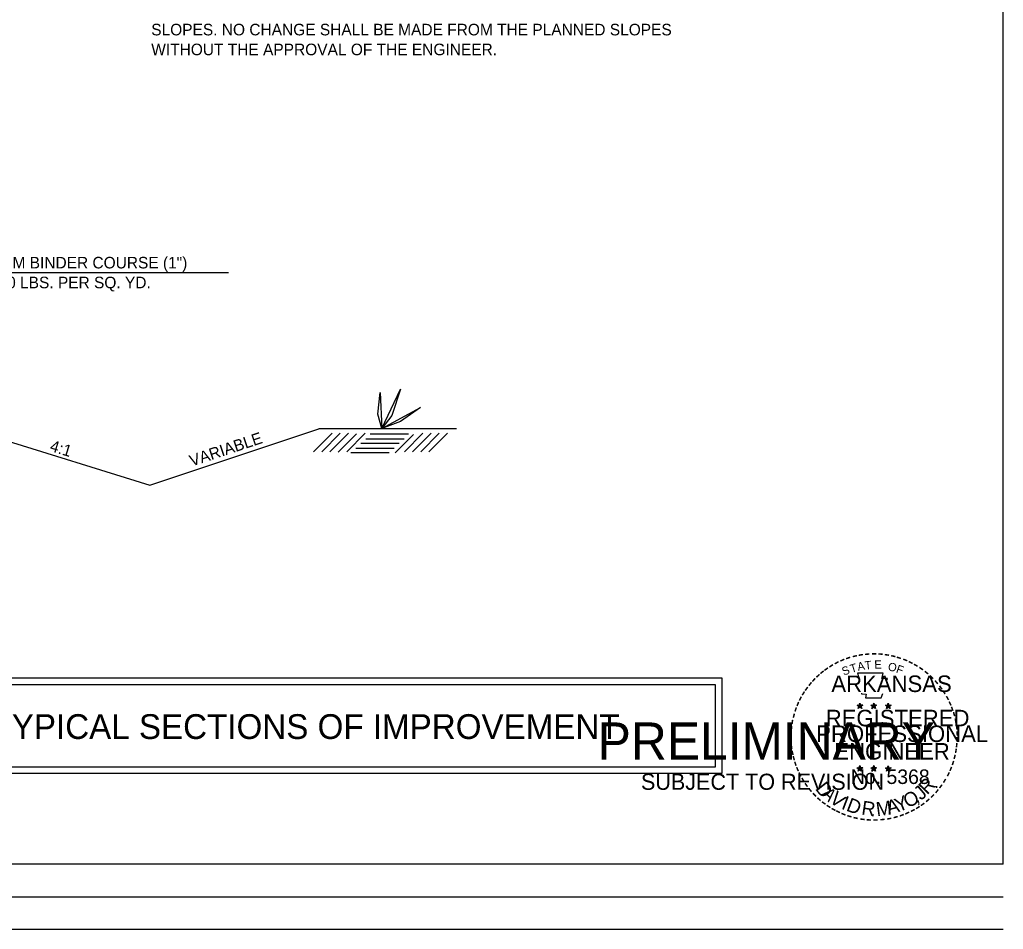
# Model space of a CAD drawing. Extents: x 1944905 to 1956777, y 763871 to 764977.
# Drawn here: x 1945928 to 1946523, y 763871 to 764421 of the extents above; entities that cross this region are included whole.
import ezdxf

# ---------------------------------------------------------------- set-up
doc = ezdxf.new("R2010")
doc.units = 0
doc.layers.add('Default', color=7, linetype='Continuous')
doc.layers.add('R_Border PE', color=7, linetype='Continuous')

msp = doc.modelspace()

# ---------------------------------------------------------------- linework, layer by layer
at = {"layer": 'Default'}
for p, q in [((1946523.23, 763910.07), (1946523.23, 764937.29)), ((1945703.81, 764268.09), (1946054.49, 764268.09)), ((1946144.78, 764182.39), (1946146.22, 764195.62)), ((1946146.22, 764195.62), (1946147.19, 764173.75)), ((1946147.19, 764173.75), (1946158.48, 764197.54)), ((1946158.48, 764197.54), (1946153.19, 764181.67)), ((1946147.19, 764173.75), (1946170.49, 764186.48)), ((1946170.49, 764186.48), (1946158.48, 764178.07)), ((1945878.1, 764179.33), (1946006.89, 764139.54)), ((1946147.19, 764173.75), (1946144.78, 764182.39)), ((1946153.19, 764181.67), (1946147.19, 764173.75)), ((1946158.48, 764178.07), (1946147.19, 764173.75)), ((1946006.89, 764139.54), (1946108.97, 764173.57)), ((1946117.08, 764170.92), (1946105.89, 764159.72)), ((1946192.37, 764173.57), (1946108.97, 764173.57)), ((1946122.02, 764170.92), (1946110.82, 764159.72)), ((1946126.95, 764170.92), (1946115.76, 764159.72)), ((1946137.18, 764170.92), (1946125.99, 764159.72)), ((1946172.07, 764170.92), (1946160.88, 764159.72)), ((1946177.01, 764170.92), (1946165.82, 764159.72)), ((1946181.93, 764170.92), (1946170.74, 764159.72)), ((1946186.87, 764170.92), (1946175.68, 764159.72)), ((1946131.87, 764170.55), (1946120.68, 764159.36)), ((1946134.53, 764164.85), (1946157.66, 764164.85)), ((1946137.56, 764167.51), (1946160.7, 764167.51)), ((1946140.21, 764170.55), (1946163.35, 764170.55)), ((1946166.38, 764170.17), (1946155.19, 764158.97)), ((1946128.46, 764159.16), (1946151.59, 764159.16)), ((1946131.49, 764161.81), (1946154.63, 764161.81)), ((1946523.23, 763910.07), (1944942.33, 763910.07)), ((1944909.48, 763890.36), (1946523.23, 763890.36)), ((1944909.48, 763870.67), (1946523.23, 763870.67))]:
    msp.add_line(p, q, dxfattribs=at)
for points in [[(1945905.63, 764022.9), (1946352.9, 764022.9), (1946352.9, 763964.87), (1945905.63, 763964.87)], [(1945909.63, 764018.9), (1946348.9, 764018.9), (1946348.9, 763968.87), (1945909.63, 763968.87)]]:
    msp.add_lwpolyline(points, close=True, dxfattribs=at)
at = {"layer": 'R_Border PE'}
for p, q in [((1946434.73, 764006.32), (1946436.43, 764005.77)), ((1946434.73, 764006.32), (1946435.98, 764006.17)), ((1946434.73, 764006.32), (1946435.98, 764006.12)), ((1946434.73, 764006.32), (1946435.93, 764006.02)), ((1946434.73, 764006.32), (1946435.93, 764005.82)), ((1946434.73, 764006.32), (1946435.88, 764005.72)), ((1946434.73, 764006.32), (1946435.88, 764005.62)), ((1946435.38, 764004.27), (1946436.43, 764005.77)), ((1946435.38, 764004.27), (1946435.93, 764005.67)), ((1946435.38, 764004.27), (1946435.98, 764005.52)), ((1946435.38, 764004.27), (1946436.08, 764005.47)), ((1946435.38, 764004.27), (1946436.43, 764005.37)), ((1946435.38, 764004.27), (1946436.23, 764005.32)), ((1946435.38, 764004.27), (1946436.48, 764005.22)), ((1946436.43, 764007.57), (1946436.18, 764006.37)), ((1946436.43, 764007.57), (1946436.23, 764006.32)), ((1946436.43, 764007.57), (1946436.38, 764006.32)), ((1946436.43, 764005.77), (1946436.43, 764007.57)), ((1946436.43, 764007.57), (1946436.78, 764006.32)), ((1946436.43, 764007.57), (1946436.68, 764006.32)), ((1946436.43, 764007.57), (1946436.58, 764006.37)), ((1946438.18, 764006.32), (1946436.43, 764005.77)), ((1946437.53, 764004.27), (1946436.43, 764005.77)), ((1946437.53, 764004.27), (1946436.43, 764005.37)), ((1946437.53, 764004.27), (1946436.43, 764005.22)), ((1946437.53, 764004.27), (1946436.63, 764005.32)), ((1946438.18, 764006.32), (1946436.68, 764006.22)), ((1946438.18, 764006.32), (1946436.78, 764006.07)), ((1946438.18, 764006.32), (1946436.78, 764005.97)), ((1946437.53, 764004.27), (1946436.78, 764005.52)), ((1946437.53, 764004.27), (1946436.83, 764005.72)), ((1946437.53, 764004.27), (1946436.93, 764005.72)), ((1946438.18, 764006.32), (1946437.08, 764005.87)), ((1946438.18, 764006.32), (1946437.18, 764005.82)), ((1946438.18, 764006.32), (1946437.23, 764005.77)), ((1946443.03, 764006.32), (1946444.78, 764005.77)), ((1946443.03, 764006.32), (1946444.33, 764006.17)), ((1946443.03, 764006.32), (1946444.33, 764006.12)), ((1946443.03, 764006.32), (1946444.28, 764006.02)), ((1946443.03, 764006.32), (1946444.28, 764005.82)), ((1946443.03, 764006.32), (1946444.23, 764005.72)), ((1946443.03, 764006.32), (1946444.23, 764005.62)), ((1946443.73, 764004.27), (1946444.78, 764005.77)), ((1946443.73, 764004.27), (1946444.28, 764005.67)), ((1946443.73, 764004.27), (1946444.33, 764005.52)), ((1946443.73, 764004.27), (1946444.43, 764005.47)), ((1946443.73, 764004.27), (1946444.78, 764005.37)), ((1946443.73, 764004.27), (1946444.58, 764005.32)), ((1946443.73, 764004.27), (1946444.83, 764005.22)), ((1946444.78, 764007.57), (1946444.53, 764006.37)), ((1946444.78, 764007.57), (1946444.58, 764006.32)), ((1946444.78, 764007.57), (1946444.73, 764006.32)), ((1946444.78, 764005.77), (1946444.78, 764007.57)), ((1946444.78, 764007.57), (1946445.13, 764006.32)), ((1946444.78, 764007.57), (1946445.03, 764006.32)), ((1946444.78, 764007.57), (1946444.93, 764006.37)), ((1946446.53, 764006.32), (1946444.78, 764005.77)), ((1946445.88, 764004.27), (1946444.78, 764005.77)), ((1946445.88, 764004.27), (1946444.78, 764005.37)), ((1946445.88, 764004.27), (1946444.78, 764005.22)), ((1946446.53, 764006.32), (1946444.98, 764006.22)), ((1946445.88, 764004.27), (1946444.98, 764005.32)), ((1946446.53, 764006.32), (1946445.08, 764006.07)), ((1946446.53, 764006.32), (1946445.08, 764005.97)), ((1946445.88, 764004.27), (1946445.13, 764005.52)), ((1946445.88, 764004.27), (1946445.18, 764005.72)), ((1946445.88, 764004.27), (1946445.28, 764005.72)), ((1946446.53, 764006.32), (1946445.43, 764005.87)), ((1946446.53, 764006.32), (1946445.53, 764005.82)), ((1946446.53, 764006.32), (1946445.58, 764005.77)), ((1946451.88, 764006.27), (1946453.63, 764005.72)), ((1946451.88, 764006.27), (1946453.18, 764006.12)), ((1946451.88, 764006.27), (1946453.18, 764006.02)), ((1946451.88, 764006.27), (1946453.13, 764005.92)), ((1946451.88, 764006.27), (1946453.08, 764005.77)), ((1946451.88, 764006.27), (1946453.08, 764005.67)), ((1946451.88, 764006.27), (1946453.08, 764005.57)), ((1946452.58, 764004.22), (1946453.63, 764005.72)), ((1946452.58, 764004.22), (1946453.13, 764005.62)), ((1946452.58, 764004.22), (1946453.18, 764005.42)), ((1946452.58, 764004.22), (1946453.28, 764005.42)), ((1946452.58, 764004.22), (1946453.63, 764005.32)), ((1946452.58, 764004.22), (1946453.43, 764005.27)), ((1946452.58, 764004.22), (1946453.68, 764005.17)), ((1946453.63, 764007.52), (1946453.33, 764006.32)), ((1946453.63, 764007.52), (1946453.43, 764006.27)), ((1946453.63, 764007.52), (1946453.53, 764006.27)), ((1946453.63, 764005.72), (1946453.63, 764007.52)), ((1946453.63, 764007.52), (1946453.98, 764006.27)), ((1946453.63, 764007.52), (1946453.88, 764006.27)), ((1946453.63, 764007.52), (1946453.73, 764006.32)), ((1946455.38, 764006.27), (1946453.63, 764005.72)), ((1946454.68, 764004.22), (1946453.63, 764005.72)), ((1946454.68, 764004.22), (1946453.63, 764005.32)), ((1946454.68, 764004.22), (1946453.63, 764005.17)), ((1946455.38, 764006.27), (1946453.83, 764006.17)), ((1946454.68, 764004.22), (1946453.83, 764005.27)), ((1946455.38, 764006.27), (1946453.93, 764006.02)), ((1946455.38, 764006.27), (1946453.93, 764005.92)), ((1946454.68, 764004.22), (1946453.98, 764005.47)), ((1946454.68, 764004.22), (1946454.03, 764005.67)), ((1946454.68, 764004.22), (1946454.13, 764005.67)), ((1946455.38, 764006.27), (1946454.28, 764005.82)), ((1946455.38, 764006.27), (1946454.33, 764005.77)), ((1946455.38, 764006.27), (1946454.43, 764005.72)), ((1946434.68, 763968.47), (1946436.43, 763967.92)), ((1946434.68, 763968.47), (1946435.98, 763968.32)), ((1946434.68, 763968.47), (1946435.98, 763968.22)), ((1946434.68, 763968.47), (1946435.93, 763968.12)), ((1946434.68, 763968.47), (1946435.88, 763967.97)), ((1946434.68, 763968.47), (1946435.88, 763967.87)), ((1946434.68, 763968.47), (1946435.88, 763967.72)), ((1946436.43, 763969.72), (1946436.13, 763968.52)), ((1946436.43, 763969.72), (1946436.23, 763968.47)), ((1946436.43, 763969.72), (1946436.33, 763968.47)), ((1946436.43, 763967.92), (1946436.43, 763969.72)), ((1946436.43, 763969.72), (1946436.78, 763968.47)), ((1946436.43, 763969.72), (1946436.68, 763968.47)), ((1946436.43, 763969.72), (1946436.53, 763968.47)), ((1946438.18, 763968.47), (1946436.43, 763967.92)), ((1946438.18, 763968.47), (1946436.63, 763968.37)), ((1946438.18, 763968.47), (1946436.73, 763968.22)), ((1946438.18, 763968.47), (1946436.73, 763968.12)), ((1946438.18, 763968.47), (1946437.08, 763968.02)), ((1946438.18, 763968.47), (1946437.13, 763967.97)), ((1946438.18, 763968.47), (1946437.23, 763967.87)), ((1946443.03, 763968.47), (1946444.78, 763967.92)), ((1946443.03, 763968.47), (1946444.33, 763968.32)), ((1946443.03, 763968.47), (1946444.28, 763968.22)), ((1946443.03, 763968.47), (1946444.28, 763968.12)), ((1946443.03, 763968.47), (1946444.23, 763967.97)), ((1946443.03, 763968.47), (1946444.23, 763967.87)), ((1946443.03, 763968.47), (1946444.23, 763967.72)), ((1946444.78, 763969.72), (1946444.48, 763968.52)), ((1946444.78, 763969.72), (1946444.58, 763968.47)), ((1946444.78, 763969.72), (1946444.68, 763968.47)), ((1946444.78, 763967.92), (1946444.78, 763969.72)), ((1946444.78, 763969.72), (1946445.13, 763968.47)), ((1946444.78, 763969.72), (1946445.03, 763968.47)), ((1946444.78, 763969.72), (1946444.88, 763968.47)), ((1946446.53, 763968.47), (1946444.78, 763967.92)), ((1946446.53, 763968.47), (1946444.98, 763968.37)), ((1946446.53, 763968.47), (1946445.08, 763968.22)), ((1946446.53, 763968.47), (1946445.08, 763968.12)), ((1946446.53, 763968.47), (1946445.38, 763968.02)), ((1946446.53, 763968.47), (1946445.48, 763967.97)), ((1946446.53, 763968.47), (1946445.58, 763967.87)), ((1946451.88, 763968.42), (1946453.63, 763967.82)), ((1946451.88, 763968.42), (1946453.13, 763968.27)), ((1946451.88, 763968.42), (1946453.13, 763968.17)), ((1946451.88, 763968.42), (1946453.08, 763968.07)), ((1946451.88, 763968.42), (1946453.08, 763967.92)), ((1946451.88, 763968.42), (1946453.03, 763967.77)), ((1946451.88, 763968.42), (1946453.03, 763967.67)), ((1946453.63, 763969.67), (1946453.33, 763968.42)), ((1946453.63, 763969.67), (1946453.43, 763968.42)), ((1946453.63, 763969.67), (1946453.53, 763968.42)), ((1946453.63, 763967.82), (1946453.63, 763969.67)), ((1946453.63, 763969.67), (1946453.93, 763968.42)), ((1946453.63, 763969.67), (1946453.88, 763968.42)), ((1946453.63, 763969.67), (1946453.73, 763968.42)), ((1946455.33, 763968.42), (1946453.63, 763967.82)), ((1946455.33, 763968.42), (1946453.83, 763968.27)), ((1946455.33, 763968.42), (1946453.93, 763968.17)), ((1946455.33, 763968.42), (1946453.93, 763968.07)), ((1946455.33, 763968.42), (1946454.23, 763967.92)), ((1946455.33, 763968.42), (1946454.33, 763967.87)), ((1946455.33, 763968.42), (1946454.38, 763967.82)), ((1946435.38, 763966.42), (1946436.43, 763967.92)), ((1946435.38, 763966.42), (1946435.93, 763967.82)), ((1946435.38, 763966.42), (1946435.98, 763967.62)), ((1946435.38, 763966.42), (1946436.08, 763967.57)), ((1946435.38, 763966.42), (1946436.43, 763967.52)), ((1946435.38, 763966.42), (1946436.23, 763967.47)), ((1946435.38, 763966.42), (1946436.48, 763967.37)), ((1946437.48, 763966.42), (1946436.43, 763967.92)), ((1946437.48, 763966.42), (1946436.43, 763967.47)), ((1946437.48, 763966.42), (1946436.43, 763967.37)), ((1946437.48, 763966.42), (1946436.63, 763967.47)), ((1946437.48, 763966.42), (1946436.78, 763967.62)), ((1946437.48, 763966.42), (1946436.83, 763967.87)), ((1946437.48, 763966.42), (1946436.93, 763967.87)), ((1946443.68, 763966.42), (1946444.78, 763967.92)), ((1946443.68, 763966.42), (1946444.28, 763967.82)), ((1946443.68, 763966.42), (1946444.33, 763967.62)), ((1946443.68, 763966.42), (1946444.43, 763967.57)), ((1946443.68, 763966.42), (1946444.78, 763967.52)), ((1946443.68, 763966.42), (1946444.58, 763967.47)), ((1946443.68, 763966.42), (1946444.78, 763967.37)), ((1946445.83, 763966.42), (1946444.78, 763967.92)), ((1946445.83, 763966.42), (1946444.78, 763967.47)), ((1946445.83, 763966.42), (1946444.78, 763967.37)), ((1946445.83, 763966.42), (1946444.98, 763967.47)), ((1946445.83, 763966.42), (1946445.13, 763967.62)), ((1946445.83, 763966.42), (1946445.18, 763967.87)), ((1946445.83, 763966.42), (1946445.28, 763967.87)), ((1946452.53, 763966.37), (1946453.63, 763967.82)), ((1946452.53, 763966.37), (1946453.08, 763967.72)), ((1946452.53, 763966.37), (1946453.18, 763967.57)), ((1946452.53, 763966.37), (1946453.28, 763967.52)), ((1946452.53, 763966.37), (1946453.43, 763967.42)), ((1946452.53, 763966.37), (1946453.58, 763967.42)), ((1946452.53, 763966.37), (1946453.63, 763967.32)), ((1946454.68, 763966.37), (1946453.58, 763967.42)), ((1946454.68, 763966.37), (1946453.58, 763967.27)), ((1946454.68, 763966.37), (1946453.63, 763967.82)), ((1946454.68, 763966.37), (1946453.78, 763967.42)), ((1946454.68, 763966.37), (1946453.98, 763967.82)), ((1946454.68, 763966.37), (1946453.98, 763967.57)), ((1946454.68, 763966.37), (1946454.13, 763967.82))]:
    msp.add_line(p, q, dxfattribs=at)
for points in [[(1946434.93, 764025.72), (1946436.28, 764021.57)], [(1946452.48, 764021.12), (1946453.18, 764022.52), (1946449.73, 764022.42), (1946450.48, 764025.72), (1946434.93, 764025.72)], [(1946437.38, 764013.62), (1946437.38, 764013.17), (1946440.18, 764013.07), (1946439.93, 764010.72), (1946449.28, 764010.72), (1946450.28, 764013.37)], [(1946436.43, 764007.57), (1946437.53, 764004.27), (1946434.73, 764006.32), (1946438.18, 764006.32), (1946435.38, 764004.27), (1946436.43, 764007.57)], [(1946444.78, 764007.57), (1946445.88, 764004.27), (1946443.03, 764006.32), (1946446.53, 764006.32), (1946443.73, 764004.27), (1946444.78, 764007.57)], [(1946453.63, 764007.52), (1946454.68, 764004.22), (1946451.88, 764006.27), (1946455.38, 764006.27), (1946452.58, 764004.22), (1946453.63, 764007.52)], [(1946436.43, 763969.72), (1946437.48, 763966.42), (1946434.68, 763968.47), (1946438.18, 763968.47), (1946435.38, 763966.42), (1946436.43, 763969.72)], [(1946444.78, 763969.72), (1946445.83, 763966.42), (1946443.03, 763968.47), (1946446.53, 763968.47), (1946443.68, 763966.42), (1946444.78, 763969.72)], [(1946453.63, 763969.67), (1946454.68, 763966.37), (1946451.88, 763968.42), (1946455.33, 763968.42), (1946452.53, 763966.37), (1946453.63, 763969.67)]]:
    msp.add_lwpolyline(points, dxfattribs=at)
for centre, radius in [((1946436.43, 764005.77), 0.861), ((1946436.43, 764005.77), 0.78), ((1946436.43, 764005.77), 0.723), ((1946436.43, 764005.77), 0.664), ((1946436.43, 764005.77), 0.579), ((1946436.43, 764005.77), 0.537), ((1946436.43, 764005.77), 0.495), ((1946436.43, 764005.77), 0.426), ((1946436.43, 764005.77), 0.374), ((1946436.43, 764005.77), 0.311), ((1946436.43, 764005.77), 0.248), ((1946436.43, 764005.77), 0.185), ((1946436.43, 764005.77), 0.148), ((1946436.43, 764005.77), 0.0721), ((1946444.78, 764005.77), 0.861), ((1946444.78, 764005.77), 0.78), ((1946444.78, 764005.77), 0.723), ((1946444.78, 764005.77), 0.664), ((1946444.78, 764005.77), 0.579), ((1946444.78, 764005.77), 0.537), ((1946444.78, 764005.77), 0.495), ((1946444.78, 764005.77), 0.426), ((1946444.78, 764005.77), 0.374), ((1946444.78, 764005.77), 0.311), ((1946444.78, 764005.77), 0.248), ((1946444.78, 764005.77), 0.185), ((1946444.78, 764005.77), 0.148), ((1946444.78, 764005.77), 0.0721), ((1946453.62, 764005.71), 0.861), ((1946453.62, 764005.71), 0.78), ((1946453.62, 764005.71), 0.723), ((1946453.62, 764005.71), 0.664), ((1946453.62, 764005.71), 0.579), ((1946453.62, 764005.71), 0.537), ((1946453.62, 764005.71), 0.495), ((1946453.62, 764005.71), 0.426), ((1946453.62, 764005.71), 0.374), ((1946453.62, 764005.71), 0.311), ((1946453.62, 764005.71), 0.248), ((1946453.62, 764005.71), 0.185), ((1946453.62, 764005.71), 0.148), ((1946453.62, 764005.71), 0.0721), ((1946436.41, 763967.9), 0.861), ((1946436.41, 763967.9), 0.78), ((1946436.41, 763967.9), 0.723), ((1946436.41, 763967.9), 0.664), ((1946436.41, 763967.9), 0.579), ((1946436.41, 763967.9), 0.537), ((1946436.41, 763967.9), 0.495), ((1946436.41, 763967.9), 0.426), ((1946436.41, 763967.9), 0.374), ((1946444.76, 763967.9), 0.861), ((1946444.76, 763967.9), 0.78), ((1946444.76, 763967.9), 0.723), ((1946444.76, 763967.9), 0.664), ((1946444.76, 763967.9), 0.579), ((1946444.76, 763967.9), 0.537), ((1946444.76, 763967.9), 0.495), ((1946444.76, 763967.9), 0.426), ((1946444.76, 763967.9), 0.374), ((1946453.59, 763967.84), 0.861), ((1946453.59, 763967.84), 0.78), ((1946453.59, 763967.84), 0.723), ((1946453.59, 763967.84), 0.664), ((1946453.59, 763967.84), 0.579), ((1946453.59, 763967.84), 0.537), ((1946453.59, 763967.84), 0.495), ((1946453.59, 763967.84), 0.426), ((1946436.41, 763967.9), 0.311), ((1946436.41, 763967.9), 0.248), ((1946436.41, 763967.9), 0.185), ((1946436.41, 763967.9), 0.148), ((1946436.41, 763967.9), 0.0721), ((1946444.76, 763967.9), 0.311), ((1946444.76, 763967.9), 0.248), ((1946444.76, 763967.9), 0.185), ((1946444.76, 763967.9), 0.148), ((1946444.76, 763967.9), 0.0721), ((1946453.59, 763967.84), 0.374), ((1946453.59, 763967.84), 0.311), ((1946453.59, 763967.84), 0.248), ((1946453.59, 763967.84), 0.185), ((1946453.59, 763967.84), 0.148), ((1946453.59, 763967.84), 0.0721)]:
    msp.add_circle(centre, radius, dxfattribs=at)

# ---------------------------------------------------------------- texts
at = {"layer": 'Default'}
for s, height, p in [('SLOPES. NO CHANGE SHALL BE MADE FROM THE PLANNED SLOPES', 7.0054, (1946007.66, 764411.63)), ('WITHOUT THE APPROVAL OF THE ENGINEER.', 7.0054, (1946007.66, 764399.62)), ('14\'-0" ACHM BINDER COURSE (1")', 7, (1945877.51, 764270.6)), ('330 LBS. PER SQ. YD.', 7, (1945910.07, 764258.59)), ('TYPICAL SECTIONS OF IMPROVEMENT', 15, (1945911.02, 763985.86)), ('PRELIMINARY', 22.5, (1946277.82, 763973.37)), ('        SUBJECT TO REVISION', 9.75, (1946275, 763955.1))]:
    msp.add_text(s, height=height, dxfattribs=at).set_placement(p)
for s, rotation, p in [('VARIABLE', 18.37249, (1946032.12, 764150.65)), ('4:1', 342.9685, (1945945.85, 764160.25))]:
    msp.add_text(s, height=7, rotation=rotation, dxfattribs=at).set_placement(p)
at = {"layer": 'R_Border PE'}
for s, height, rotation, p in [('-', 8, 24.30721, (1946425.48, 764030.02)), ('-', 8, 19.17608, (1946428.63, 764031.37)), ('-', 8, 13.63015, (1946432.38, 764032.57)), ('-', 8, 10.21935, (1946435.78, 764033.37)), ('-', 8, 5.89682, (1946439.43, 764033.92)), ('-', 8, 0.18623, (1946443.28, 764034.27)), ('-', 8, 357.74304, (1946446.93, 764034.22)), ('-', 8, 352.16173, (1946450.63, 764033.92)), ('-', 8, 347.20489, (1946454.23, 764033.37)), ('-', 8, 342.3362, (1946457.38, 764032.57)), ('-', 8, 337.85509, (1946461.08, 764031.47)), ('-', 8, 36.23174, (1946416.43, 764024.57)), ('-', 8, 34.06357, (1946419.33, 764026.57)), ('-', 8, 28.79182, (1946422.33, 764028.42)), ('S', 5, 21.59401, (1946426.68, 764024.12)), ('T', 5, 16.4036, (1946431.28, 764025.77)), ('A', 5, 11.21318, (1946435.38, 764027.02)), ('T', 5, 6.02276, (1946439.63, 764027.82)), ('E', 5, 0.83234, (1946445.18, 764028.37)), ('O', 5, 350.4515, (1946453.18, 764027.32)), ('F', 5, 340.07066, (1946457.93, 764026.22)), ('-', 8, 334.12109, (1946464.23, 764030.12)), ('-', 8, 329.64089, (1946467.13, 764028.72)), ('-', 8, 325.86266, (1946470.33, 764026.87)), ('-', 8, 48.42305, (1946409.68, 764018.22)), ('-', 8, 42.96224, (1946411.88, 764020.62)), ('-', 8, 38.95066, (1946414.08, 764022.72)), ('-', 8, 320.52971, (1946473.38, 764024.77)), ('-', 8, 315.57859, (1946476.38, 764022.32)), ('-', 8, 54.23247, (1946405.58, 764012.97)), ('-', 8, 50.61417, (1946407.63, 764015.82)), ('-', 8, 309.87973, (1946479.23, 764019.57)), ('-', 8, 306.65218, (1946481.88, 764016.57)), ('-', 8, 62.87135, (1946402.38, 764007.27)), ('-', 8, 58.07063, (1946403.93, 764010.32)), ('-', 7, 303.67529, (1946484.28, 764013.72)), ('-', 8, 299.66835, (1946485.88, 764010.67)), ('-', 8, 72.39447, (1946399.98, 764001.07)), ('-', 8, 67.77427, (1946401.08, 764004.22)), ('-', 8, 294.66279, (1946487.48, 764007.62)), ('-', 8, 290.57283, (1946488.78, 764004.72)), ('-', 8, 75.46096, (1946399.03, 763997.47)), ('-', 8, 285.12326, (1946489.98, 764001.82)), ('-', 8, 280.54934, (1946490.98, 763998.12)), ('-', 8, 85.18634, (1946397.98, 763990.47)), ('-', 8, 81.20126, (1946398.33, 763993.92)), ('-', 8, 276.59616, (1946491.78, 763994.27)), ('-', 8, 94.19588, (1946398.03, 763983.32)), ('-', 8, 89.06224, (1946397.83, 763986.97)), ('-', 8, 274.33011, (1946492.08, 763990.67)), ('-', 8, 269.94067, (1946492.23, 763987.52)), ('-', 8, 98.94793, (1946398.38, 763980.02)), ('-', 8, 263.5172, (1946492.13, 763984.17)), ('-', 8, 101.71495, (1946399.08, 763976.32)), ('-', 8, 105.45785, (1946399.88, 763973.37)), ('-', 8, 255.7626, (1946491.23, 763977.52)), ('-', 8, 260.99529, (1946491.78, 763980.92)), ('-', 8, 109.08742, (1946400.93, 763970.22)), ('-', 8, 114.06432, (1946402.23, 763967.22)), ('-', 8, 247.88866, (1946489.23, 763970.57)), ('-', 8, 252.86809, (1946490.33, 763973.92)), ('-', 8, 115.72885, (1946403.73, 763964.12)), ('-', 8, 120.44712, (1946405.53, 763961.22)), ('-', 8, 244.61971, (1946487.93, 763967.42)), ('-', 8, 125.89344, (1946407.53, 763958.42)), ('D', 8.47, 308.02669, (1946409.08, 763955.72)), ('J', 8.47, 40.15065, (1946473.43, 763948.37)), ('R', 8.47, 46.29225, (1946477.18, 763951.72)), ('-', 8, 233.84524, (1946483.93, 763960.42)), ('-', 8, 239.07125, (1946485.93, 763963.67)), ('-', 8, 130.71812, (1946409.83, 763955.62)), ('-', 8, 134.22381, (1946412.43, 763952.92)), ('-', 8, 138.93382, (1946415.08, 763950.57)), ('A', 7.7, 314.16829, (1946412.83, 763952.27)), ('V', 8.47, 322.07513, (1946417.48, 763948.22)), ('ID', 8.47, 339.24466, (1946424.73, 763943.77)), ('Y', 8.47, 21.72586, (1946459.53, 763941.37)), ('O', 8.47, 27.86746, (1946465.43, 763943.77)), ('-', 8, 225.76533, (1946479.38, 763954.77)), ('-', 8, 231.25377, (1946481.78, 763957.57)), ('-', 8, 144.64634, (1946417.83, 763948.57)), ('-', 8, 148.08978, (1946420.63, 763946.72)), ('R', 8.47, 351.48461, (1946437.03, 763940.22)), ('M', 8.47, 7.38422, (1946446.73, 763939.07)), ('A', 8.47, 15.04444, (1946453.73, 763940.02)), ('-', 8, 212.24909, (1946471.38, 763947.92)), (',', 8.45, 13.66842, (1946470.28, 763947.02)), ('-', 8, 215.73633, (1946474.03, 763949.82)), ('-', 8, 221.08509, (1946476.78, 763952.22)), ('-', 8, 151.57039, (1946423.53, 763945.07)), ('-', 8, 154.60019, (1946426.13, 763943.87)), ('-', 8, 158.56121, (1946429.28, 763942.57)), ('-', 8, 162.79826, (1946432.68, 763941.52)), ('-', 8, 167.55551, (1946436.28, 763940.67)), ('.', 7.7, 351.01787, (1946442.83, 763939.27)), ('-', 8, 195.47429, (1946458.98, 763942.02)), ('-', 8, 200.71842, (1946462.33, 763943.22)), ('-', 8, 204.25161, (1946465.43, 763944.57)), ('-', 8, 207.35684, (1946468.58, 763946.17)), ('-', 8, 173.11546, (1946440.13, 763940.12)), ('-', 8, 176.51827, (1946443.88, 763939.87)), ('-', 8, 181.59176, (1946447.58, 763939.97)), ('-', 8, 185.81666, (1946451.63, 763940.37)), ('-', 8, 191.28576, (1946455.33, 763941.02))]:
    msp.add_text(s, height=height, rotation=rotation, dxfattribs=at).set_placement(p)
for s, height, p in [('ARKANSAS', 10, (1946419.18, 764014.27)), ('REGISTERED', 10, (1946415.78, 763993.52)), ('PROFESSIONAL', 9.9999, (1946410.03, 763984.02)), ('ENGINEER', 10, (1946420.98, 763973.37)), ('No. 5368', 8.785, (1946430.98, 763958.62)), ('.', 8.45, (1946481.23, 763956.12))]:
    msp.add_text(s, height=height, dxfattribs=at).set_placement(p)

doc.saveas('drawing.dxf')
